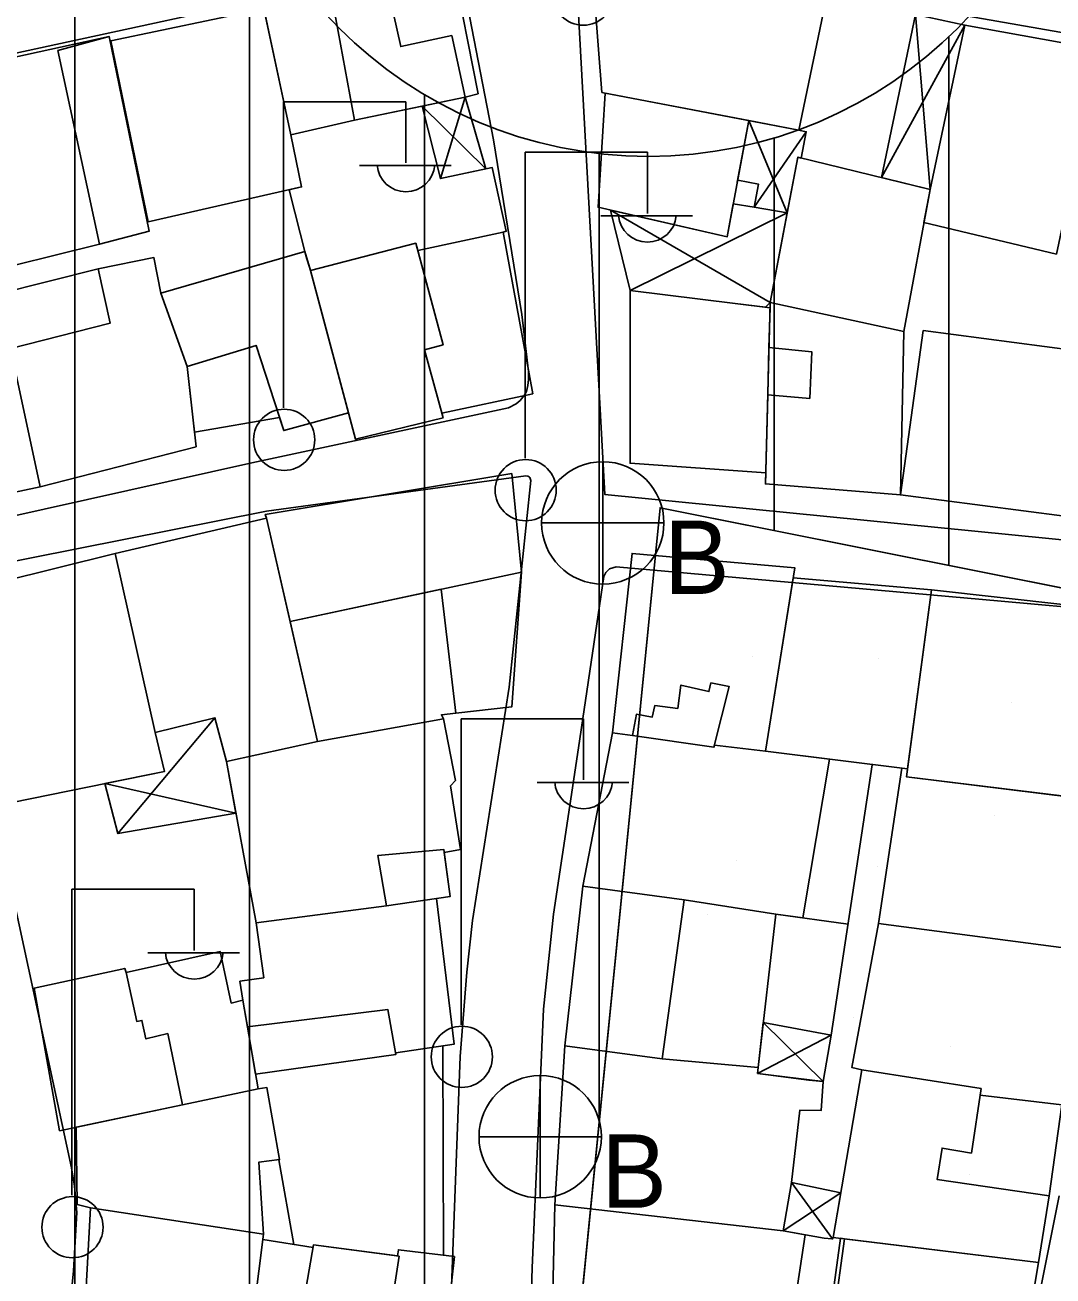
# Model space of a CAD drawing. Extents: x 417997 to 421451, y 4451742 to 4455216.
# Drawn here: x 419279.9 to 419338.7, y 4453287.2 to 4453358.7 of the extents above; entities that cross this region are included whole.
import ezdxf

# ---------------------------------------------------------------- set-up
doc = ezdxf.new("R2010")
doc.units = 0
for name, color, linetype in [('ADA', 7, 'Continuous'), ('B_Mesken', 7, 'Continuous'), ('B_Sundurma', 7, 'Continuous'), ('B_Teras', 7, 'Continuous'), ('Default', 7, 'Continuous'), ('PL_AYA_PARK_DINLENME', 7, 'Continuous'), ('PL_KON_MEV_350', 7, 'Continuous'), ('S_Elektrik_Diregi', 7, 'Continuous'), ('S_Rogar_Kapagi_Buski', 7, 'Continuous'), ('Sinir_Duvar_tek_tarafa_ait', 7, 'Continuous'), ('Sinir_Tel_bir_taraf', 7, 'Continuous'), ('SM_DAIRE', 7, 'Continuous'), ('TR_ORTAYOGUNKONUT', 7, 'Continuous'), ('TR_PARKALANI', 7, 'Continuous'), ('Yol_Sose', 7, 'Continuous')]:
    doc.layers.add(name, color=color, linetype=linetype)

# ---------------------------------------------------------------- blocks, each defined once
blk = doc.blocks.new('POINT_DISPLAY')
at = {"layer": 'Default'}
blk.add_line((0, 0), (0, 0), dxfattribs=at)

msp = doc.modelspace()

# ---------------------------------------------------------------- linework, layer by layer
at = {"layer": 'ADA'}
for p, q in [((419316.258, 4453331.104), (419309.63, 4453264.279)), ((419316.258, 4453331.104), (419309.63, 4453264.279)), ((419346.633, 4453325.029), (419316.258, 4453331.104)), ((419346.633, 4453325.029), (419316.258, 4453331.104))]:
    msp.add_line(p, q, dxfattribs=at)
at = {"layer": 'B_Mesken'}
for points in [[(419312.928, 4453354.862), (419312.312, 4453362.755), (419312.933, 4453363.499), (419325.882, 4453360.77), (419324.195, 4453352.708)], [(419297.757, 4453360.817), (419304.386, 4453362.227), (419305.854, 4453354.78), (419305.105, 4453354.588), (419298.78, 4453353.266), (419297.575, 4453359.796), (419297.982, 4453359.861)], [(419297.982, 4453359.861), (419297.706, 4453361.034), (419293.491, 4453360.119), (419295.146, 4453352.426), (419298.78, 4453353.266), (419297.575, 4453359.796)], [(419286.983, 4453347.453), (419284.837, 4453357.812), (419293.592, 4453359.649), (419295.146, 4453352.426), (419295.759, 4453349.459)], [(419333.702, 4453358.711), (419341.423, 4453357.324), (419338.936, 4453345.615), (419331.353, 4453347.419), (419331.702, 4453349.313)], [(419284.186, 4453346.178), (419279.277, 4453344.951), (419279.364, 4453344.475), (419278.232, 4453344.222), (419277.975, 4453345.285), (419277.181, 4453349.423), (419275.944, 4453356.133), (419284.755, 4453358.05), (419287.043, 4453346.929)], [(419313.121, 4453354.825), (419321.333, 4453353.255), (419320.104, 4453346.608), (419312.713, 4453348.287)], [(419307.285, 4453346.861), (419302.403, 4453345.811), (419302.289, 4453346.235), (419296.256, 4453344.678), (419295.99, 4453345.529), (419295.041, 4453349.295), (419295.759, 4453349.459), (419295.146, 4453352.426), (419298.78, 4453353.266), (419302.651, 4453354.075), (419303.695, 4453349.933), (419306.662, 4453350.558), (419307.466, 4453346.916)], [(419322.558, 4453342.847), (419330.206, 4453341.191), (419331.702, 4453349.313), (419324.136, 4453351.149)], [(419308.99, 4453337.615), (419303.773, 4453336.514), (419303.846, 4453336.241), (419298.837, 4453335.022), (419296.256, 4453344.678), (419302.289, 4453346.235), (419302.403, 4453345.811), (419307.285, 4453346.861)], [(419289.723, 4453334.596), (419289.206, 4453339.183), (419287.694, 4453343.372), (419287.303, 4453345.412), (419284.114, 4453344.766), (419278.348, 4453343.313), (419279.055, 4453340.198), (419279.183, 4453339.877), (419280.797, 4453332.303)], [(419294.493, 4453336.264), (419289.628, 4453335.435), (419289.206, 4453339.183), (419287.694, 4453343.372), (419295.932, 4453345.761), (419295.99, 4453345.529), (419296.256, 4453344.678), (419298.432, 4453336.537), (419294.736, 4453335.52)], [(419270.017, 4453340.29), (419269.701, 4453341.487), (419278.348, 4453343.313), (419279.055, 4453340.198), (419279.183, 4453339.877), (419280.797, 4453332.303), (419272.114, 4453330.453), (419271.998, 4453330.996), (419271.184, 4453334.817), (419270.5, 4453338.027)], [(419322.55, 4453342.543), (419314.544, 4453343.524), (419314.546, 4453333.65), (419322.301, 4453333.103), (419322.284, 4453332.465), (419322.418, 4453337.557), (419322.49, 4453340.272)], [(419322.558, 4453342.847), (419322.284, 4453332.465), (419330.005, 4453331.834), (419330.206, 4453341.191)], [(419331.306, 4453341.243), (419345.199, 4453339.412), (419344.09, 4453330.012), (419330.005, 4453331.834)], [(419308.327, 4453327.416), (419307.775, 4453319.712), (419304.582, 4453319.356), (419303.757, 4453319.264), (419303.863, 4453319.019), (419296.662, 4453317.741), (419295.102, 4453324.591), (419293.756, 4453330.5), (419293.677, 4453330.718), (419307.776, 4453333.058)], [(419287.377, 4453318.252), (419285.093, 4453328.483), (419293.756, 4453330.5), (419296.662, 4453317.741), (419291.453, 4453316.59), (419290.797, 4453319.092)], [(419285.093, 4453328.483), (419275.176, 4453326.018), (419278.061, 4453314.014), (419287.921, 4453316.02), (419287.377, 4453318.252)], [(419314.688, 4453318.077), (419313.543, 4453318.226), (419314.658, 4453328.493), (419323.973, 4453327.663), (419322.288, 4453317.186), (419319.366, 4453317.516), (419319.337, 4453317.403)], [(419331.778, 4453326.398), (419323.882, 4453327.095), (419322.288, 4453317.186), (419330.422, 4453316.165)], [(419331.778, 4453326.398), (419330.361, 4453315.704), (419342.052, 4453314.273), (419343.226, 4453325.132)], [(419296.662, 4453317.741), (419303.863, 4453319.019), (419304.565, 4453315.503), (419304.273, 4453315.188), (419304.838, 4453311.55), (419303.914, 4453311.385), (419304.246, 4453308.858), (419300.609, 4453308.337), (419293.154, 4453307.368), (419291.453, 4453316.59)], [(419313.543, 4453318.226), (419311.838, 4453309.463), (419317.636, 4453308.666), (419322.876, 4453307.852), (419324.42, 4453307.638), (419325.952, 4453316.726), (419322.288, 4453317.186), (419319.366, 4453317.516), (419319.337, 4453317.403), (419314.688, 4453318.077)], [(419330.361, 4453315.704), (419330.422, 4453316.165), (419330.094, 4453316.206), (419328.746, 4453307.329), (419340.653, 4453305.76), (419341.763, 4453314.309)], [(419317.636, 4453308.666), (419311.838, 4453309.463), (419310.821, 4453300.328), (419316.381, 4453299.576), (419321.865, 4453299.084), (419322.876, 4453307.852)], [(419303.473, 4453308.747), (419304.48, 4453300.413), (419301.137, 4453299.929), (419301.155, 4453299.829), (419293.117, 4453298.71), (419292.653, 4453301.403), (419292.39, 4453302.927), (419292.227, 4453304.018), (419293.59, 4453304.214), (419293.154, 4453307.368), (419293.154, 4453307.368), (419300.609, 4453308.337)], [(419339.243, 4453296.941), (419340.653, 4453305.76), (419328.746, 4453307.329), (419327.226, 4453299.088), (419327.795, 4453298.947), (419334.619, 4453297.874), (419334.562, 4453297.494)], [(419285.715, 4453304.513), (419291.098, 4453305.714), (419291.735, 4453302.768), (419292.39, 4453302.927), (419293.262, 4453297.869), (419288.934, 4453296.957), (419281.916, 4453295.465), (419280.454, 4453303.617), (419285.642, 4453304.755)], [(419321.865, 4453299.084), (419321.834, 4453298.75), (419325.594, 4453298.276), (419325.472, 4453296.623), (419324.25, 4453296.637), (419323.776, 4453292.501), (419323.306, 4453289.735), (419310.236, 4453291.235), (419310.821, 4453300.328), (419316.381, 4453299.576), (419321.865, 4453299.084), (419321.834, 4453298.75)], [(419334.562, 4453297.494), (419339.243, 4453296.941), (419338.527, 4453291.751), (419337.906, 4453287.927), (419326.16, 4453289.365), (419327.795, 4453298.947), (419334.619, 4453297.874)], [(419293.262, 4453297.869), (419293.776, 4453297.933), (419294.496, 4453293.818), (419293.317, 4453293.677), (419293.575, 4453289.544), (419283.68, 4453291.064), (419282.912, 4453291.249), (419282.867, 4453295.667), (419288.934, 4453296.957), (419293.262, 4453297.869)], [(419283.271, 4453283.713), (419283.68, 4453291.064), (419293.575, 4453289.544), (419292.756, 4453283.052)], [(419310.236, 4453291.235), (419309.985, 4453280.423), (419316.902, 4453279.885), (419316.9, 4453278.561), (419322.085, 4453277.768), (419322.763, 4453277.679), (419324.566, 4453289.517), (419323.306, 4453289.735)], [(419304.51, 4453288.282), (419301.297, 4453288.656), (419301.25, 4453288.303), (419296.44, 4453288.948), (419295.339, 4453282.546), (419300.632, 4453281.831), (419303.85, 4453281.287), (419304.391, 4453284.159), (419304.046, 4453284.207)], [(419337.238, 4453283.975), (419336.349, 4453279.262), (419331.978, 4453279.916), (419331.91, 4453279.652), (419327.354, 4453280.442), (419327.303, 4453280.223), (419325.639, 4453280.536), (419325.729, 4453281.006), (419325.357, 4453281.073), (419325.538, 4453282.073), (419325.781, 4453283.427), (419326.577, 4453289.314), (419326.814, 4453289.285), (419337.906, 4453287.927)]]:
    msp.add_lwpolyline(points, close=True, dxfattribs=at)
at = {"layer": 'B_Sundurma'}
for p, q in [((419331.702, 4453349.313), (419330.875, 4453359.318)), ((419328.936, 4453349.984), (419333.702, 4453358.711)), ((419306.295, 4453350.481), (419302.651, 4453354.075)), ((419303.695, 4453349.933), (419305.105, 4453354.588)), ((419321.333, 4453353.255), (419323.533, 4453347.98)), ((419324.625, 4453352.613), (419321.645, 4453348.297)), ((419313.43, 4453348.124), (419322.558, 4453342.847)), ((419314.544, 4453343.524), (419323.533, 4453347.98)), ((419285.244, 4453312.468), (419290.797, 4453319.092)), ((419284.507, 4453315.325), (419292, 4453313.624)), ((419322.162, 4453301.66), (419325.594, 4453298.276)), ((419321.834, 4453298.75), (419326.05, 4453300.935)), ((419326.125, 4453289.276), (419323.776, 4453292.501)), ((419326.595, 4453291.918), (419323.306, 4453289.735))]:
    msp.add_line(p, q, dxfattribs=at)
for points in [[(419331.702, 4453349.313), (419328.936, 4453349.984), (419330.875, 4453359.318), (419333.702, 4453358.711)], [(419306.295, 4453350.481), (419303.695, 4453349.933), (419302.651, 4453354.075), (419305.105, 4453354.588)], [(419320.68, 4453349.722), (419321.333, 4453353.255), (419324.195, 4453352.708), (419324.625, 4453352.613), (419324.332, 4453351.101), (419324.136, 4453351.149), (419323.533, 4453347.98), (419321.645, 4453348.297), (419321.886, 4453349.619), (419320.701, 4453349.837)], [(419313.43, 4453348.124), (419314.544, 4453343.524), (419320.56, 4453342.787), (419322.297, 4453342.574), (419322.558, 4453342.847), (419323.533, 4453347.98), (419321.645, 4453348.297), (419320.45, 4453348.481), (419320.104, 4453346.608)], [(419284.507, 4453315.325), (419285.244, 4453312.468), (419292, 4453313.624), (419291.453, 4453316.59), (419290.797, 4453319.092), (419287.377, 4453318.252), (419287.921, 4453316.02)], [(419321.997, 4453298.73), (419321.834, 4453298.75), (419321.865, 4453299.084), (419322.162, 4453301.66), (419326.05, 4453300.935), (419325.594, 4453298.276), (419324.772, 4453298.357)], [(419325.652, 4453289.329), (419326.086, 4453289.275), (419326.125, 4453289.276), (419326.16, 4453289.365), (419326.595, 4453291.918), (419323.776, 4453292.501), (419323.306, 4453289.735), (419325.652, 4453289.329)]]:
    msp.add_lwpolyline(points, close=True, dxfattribs=at)
at = {"layer": 'B_Teras'}
for points in [[(419298.78, 4453353.266), (419297.575, 4453359.796), (419300.811, 4453360.311), (419301.431, 4453357.485), (419304.347, 4453358.108), (419305.105, 4453354.588)], [(419284.186, 4453346.178), (419281.812, 4453357.255), (419284.755, 4453358.05), (419287.043, 4453346.929)], [(419296.256, 4453344.678), (419302.289, 4453346.235), (419303.845, 4453340.424), (419302.793, 4453340.138), (419303.846, 4453336.241), (419298.837, 4453335.022)], [(419298.432, 4453336.537), (419294.736, 4453335.52), (419293.148, 4453340.387), (419289.206, 4453339.183), (419287.694, 4453343.372), (419295.932, 4453345.761), (419296.256, 4453344.678)], [(419279.055, 4453340.198), (419278.348, 4453343.313), (419284.114, 4453344.766), (419284.813, 4453341.661)], [(419270.5, 4453338.027), (419271.184, 4453334.817), (419272.114, 4453330.453), (419280.797, 4453332.303), (419279.183, 4453339.877)], [(419322.418, 4453337.557), (419322.49, 4453340.272), (419324.934, 4453340.021), (419324.827, 4453337.354)], [(419293.756, 4453330.5), (419293.677, 4453330.718), (419307.776, 4453333.058), (419308.327, 4453327.416), (419295.102, 4453324.591)], [(419303.744, 4453326.437), (419304.582, 4453319.356), (419303.757, 4453319.264), (419303.863, 4453319.019), (419296.662, 4453317.741), (419295.102, 4453324.591)], [(419319.337, 4453317.403), (419314.688, 4453318.077), (419314.912, 4453319.287), (419315.816, 4453319.128), (419315.953, 4453319.79), (419317.269, 4453319.624), (419317.457, 4453320.959), (419319.058, 4453320.587), (419319.167, 4453321.079), (419320.209, 4453320.878)], [(419300.609, 4453308.337), (419300.119, 4453311.219), (419303.892, 4453311.553), (419304.246, 4453308.858)], [(419310.821, 4453300.328), (419311.838, 4453309.463), (419317.636, 4453308.666), (419316.381, 4453299.576)], [(419288.934, 4453296.957), (419288.1, 4453301.024), (419286.852, 4453300.716), (419286.622, 4453301.775), (419286.327, 4453301.719), (419285.715, 4453304.513), (419291.098, 4453305.714), (419291.735, 4453302.768), (419292.39, 4453302.927), (419293.262, 4453297.869)], [(419293.117, 4453298.71), (419292.653, 4453301.403), (419300.686, 4453302.404), (419301.155, 4453299.829)], [(419326.16, 4453289.365), (419327.795, 4453298.947), (419334.619, 4453297.874), (419334.067, 4453294.191), (419332.391, 4453294.472), (419332.119, 4453292.676), (419338.527, 4453291.751), (419337.906, 4453287.927)], [(419300.632, 4453281.831), (419295.339, 4453282.546), (419296.44, 4453288.948), (419301.327, 4453288.292), (419300.79, 4453284.697), (419301.192, 4453284.601), (419304.391, 4453284.159), (419303.85, 4453281.287)], [(419326.218, 4453284.978), (419326.814, 4453289.285), (419337.906, 4453287.927), (419337.238, 4453283.975), (419333.556, 4453284.484), (419333.445, 4453284.029), (419332.552, 4453284.11), (419332.518, 4453283.663), (419330.282, 4453283.912), (419330.346, 4453284.384)]]:
    msp.add_lwpolyline(points, close=True, dxfattribs=at)
at = {"layer": 'PL_AYA_PARK_DINLENME'}
msp.add_lwpolyline([(419309.63, 4453264.279), (419316.258, 4453331.104), (419346.633, 4453325.029), (419334.483, 4453258.204)], close=True, dxfattribs=at)
msp.add_lwpolyline([(419309.63, 4453264.279), (419316.258, 4453331.104), (419346.633, 4453325.029), (419334.483, 4453258.204)], close=True, dxfattribs=at)
at = {"layer": 'PL_KON_MEV_350'}
msp.add_lwpolyline([(419538.425, 4453192.648), (419256.318, 4453238.725), (419260.478, 4453264.279), (419309.63, 4453264.279), (419334.483, 4453258.204), (419346.633, 4453325.029), (419316.258, 4453331.104), (419309.63, 4453264.279), (419260.478, 4453264.279), (419235.965, 4453267.866), (419238.042, 4453280.58), (419238.78, 4453285.867), (419239.272, 4453291.183), (419239.516, 4453296.515), (419239.513, 4453301.853), (419239.262, 4453307.185), (419238.765, 4453312.5), (419238.02, 4453317.786), (419237.032, 4453323.032), (419222.78, 4453390.072)], dxfattribs=at)
at = {"layer": 'S_Elektrik_Diregi'}
for p, q in [((419294.723, 4453336.825), (419294.723, 4453354.325)), ((419294.723, 4453354.325), (419301.723, 4453354.325)), ((419301.723, 4453350.825), (419301.723, 4453354.325)), ((419308.535, 4453333.943), (419308.535, 4453351.443)), ((419308.535, 4453351.443), (419315.535, 4453351.443)), ((419315.535, 4453347.943), (419315.535, 4453351.443)), ((419299.063, 4453350.685), (419304.313, 4453350.685)), ((419312.875, 4453347.803), (419318.125, 4453347.803)), ((419304.883, 4453301.531), (419304.883, 4453319.032)), ((419304.883, 4453319.032), (419311.883, 4453319.032)), ((419311.883, 4453315.532), (419311.883, 4453319.032)), ((419309.223, 4453315.392), (419314.473, 4453315.392)), ((419282.612, 4453291.783), (419282.612, 4453309.283)), ((419282.612, 4453309.283), (419289.612, 4453309.283)), ((419289.612, 4453305.783), (419289.612, 4453309.283)), ((419286.952, 4453305.643), (419292.202, 4453305.643))]:
    msp.add_line(p, q, dxfattribs=at)
for centre in [(419311.864, 4453360.455), (419294.759, 4453334.99), (419308.571, 4453332.107), (419304.919, 4453299.696), (419282.648, 4453289.948)]:
    msp.add_circle(centre, 1.75, dxfattribs=at)
for centre in [(419301.724, 4453350.838), (419315.536, 4453347.956), (419311.884, 4453315.544), (419289.613, 4453305.796)]:
    msp.add_arc(centre, 1.658, 184.83843, 355.14641, dxfattribs=at)
at = {"layer": 'S_Rogar_Kapagi_Buski'}
for p, q in [((419312.984, 4453333.734), (419312.984, 4453326.734)), ((419309.484, 4453330.234), (419316.484, 4453330.234)), ((419309.404, 4453298.624), (419309.404, 4453291.624)), ((419305.904, 4453295.124), (419312.904, 4453295.124))]:
    msp.add_line(p, q, dxfattribs=at)
for centre in [(419312.984, 4453330.234), (419309.404, 4453295.124)]:
    msp.add_circle(centre, 3.5, dxfattribs=at)
at = {"layer": 'Sinir_Duvar_tek_tarafa_ait'}
for points in [[(419326.05, 4453300.935), (419328.392, 4453316.395)], [(419322.876, 4453307.852), (419327.011, 4453307.278)], [(419293.537, 4453289.24), (419296.413, 4453288.795)]]:
    msp.add_lwpolyline(points, dxfattribs=at)
at = {"layer": 'Sinir_Tel_bir_taraf'}
for points in [[(419303.841, 4453300.321), (419303.871, 4453288.356)], [(419295.306, 4453288.967), (419294.451, 4453293.812)]]:
    msp.add_lwpolyline(points, dxfattribs=at)
at = {"layer": 'SM_DAIRE'}
msp.add_circle((419315.597, 4453376.202), 25, dxfattribs=at)
msp.add_circle((419315.597, 4453376.202), 25, dxfattribs=at)
at = {"layer": 'TR_ORTAYOGUNKONUT'}
for p, q in [((419282.78, 4453234.403), (419282.78, 4453414.471)), ((419282.78, 4453234.403), (419282.78, 4453414.471)), ((419292.78, 4453232.77), (419292.78, 4453365.986)), ((419292.78, 4453232.77), (419292.78, 4453365.986)), ((419332.78, 4453327.799), (419332.78, 4453358.043)), ((419332.78, 4453327.799), (419332.78, 4453358.043)), ((419302.78, 4453231.136), (419302.78, 4453354.738)), ((419302.78, 4453231.136), (419302.78, 4453354.738)), ((419322.78, 4453329.799), (419322.78, 4453352.256)), ((419322.78, 4453329.799), (419322.78, 4453352.256)), ((419312.78, 4453296.034), (419312.78, 4453351.361)), ((419312.78, 4453296.034), (419312.78, 4453351.361))]:
    msp.add_line(p, q, dxfattribs=at)
at = {"layer": 'Yol_Sose'}
for points in [[(419372.123, 4453352.542), (419311.391, 4453363.174), (419313.096, 4453331.862), (419344.839, 4453328.705), (419345.775, 4453336.79)], [(419245.082, 4453323.196), (419236.39, 4453321.53), (419236.244, 4453321.54), (419236.156, 4453321.542), (419236.037, 4453321.545), (419235.856, 4453321.7), (419235.786, 4453321.802), (419232.661, 4453335.97), (419230.655, 4453344.982), (419230.655, 4453345.042), (419230.756, 4453345.223), (419230.81, 4453345.27), (419248.958, 4453350.559), (419267.406, 4453354.648), (419274.726, 4453356.09), (419301.522, 4453361.915)], [(419304.745, 4453362.385), (419306.731, 4453352.148), (419308.359, 4453342.148), (419308.741, 4453338.904), (419308.733, 4453338.432), (419308.698, 4453338.09), (419308.626, 4453337.746), (419308.494, 4453337.521), (419308.252, 4453337.236), (419308.026, 4453337.045), (419307.587, 4453336.824), (419292.913, 4453333.68), (419278.714, 4453330.507), (419256.401, 4453325.714)], [(419274.823, 4453327.155), (419293.743, 4453330.9), (419308.591, 4453332.92), (419308.7, 4453332.903), (419308.78, 4453332.87), (419308.818, 4453332.83), (419308.86, 4453332.658), (419307.631, 4453320.837), (419305.534, 4453307.491), (419305.214, 4453304.546), (419304.828, 4453299.707), (419304.313, 4453286.052), (419303.557, 4453272.189), (419302.908, 4453264.309), (419302.846, 4453264.217), (419302.772, 4453264.149), (419302.599, 4453264.042), (419302.384, 4453263.998), (419301.619, 4453264.01), (419281.38, 4453266.335), (419281.291, 4453266.373), (419281.167, 4453266.483), (419281.133, 4453266.586), (419281.617, 4453276.335)], [(419308.446, 4453271.407), (419308.95, 4453287.623), (419309.593, 4453302.42), (419310.166, 4453307.862), (419311.587, 4453317.368), (419313.048, 4453327.168), (419313.162, 4453327.403), (419313.375, 4453327.612), (419313.74, 4453327.728), (419335.772, 4453325.762), (419341.698, 4453325.233)], [(419281.617, 4453276.335), (419282.71, 4453287.454), (419282.89, 4453290.79), (419282.766, 4453292.289), (419282.602, 4453293.337), (419279.072, 4453309.723)], [(419339.097, 4453291.753), (419335.93, 4453275.928)]]:
    msp.add_lwpolyline(points, dxfattribs=at)

# ---------------------------------------------------------------- block references
at = {"layer": 'TR_PARKALANI', "xscale": 0.1, "yscale": 0.10000000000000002}
for p in [(419321.576, 4453322.596), (419321.576, 4453322.596), (419328.756, 4453322.502), (419328.756, 4453322.502), (419336.348, 4453319.991), (419336.348, 4453319.991), (419335.416, 4453313.522), (419335.416, 4453313.522), (419320.644, 4453310.917), (419320.644, 4453310.917), (419328.724, 4453310.594), (419328.724, 4453310.594), (419318.972, 4453307.824), (419318.972, 4453307.824), (419327.305, 4453301.937), (419327.305, 4453301.937), (419332.876, 4453300.295), (419332.876, 4453300.295), (419333.965, 4453292.957), (419333.965, 4453292.957), (419319.193, 4453290.353), (419319.193, 4453290.353), (419319.831, 4453290.078), (419319.831, 4453290.078)]:
    msp.add_blockref('POINT_DISPLAY', p, dxfattribs=at)

# ---------------------------------------------------------------- texts
at = {"layer": 'S_Rogar_Kapagi_Buski'}
for p in [(419316.484, 4453326.169), (419312.904, 4453291.059)]:
    msp.add_text('B', height=4.2, dxfattribs=at).set_placement(p)

doc.saveas('drawing.dxf')
